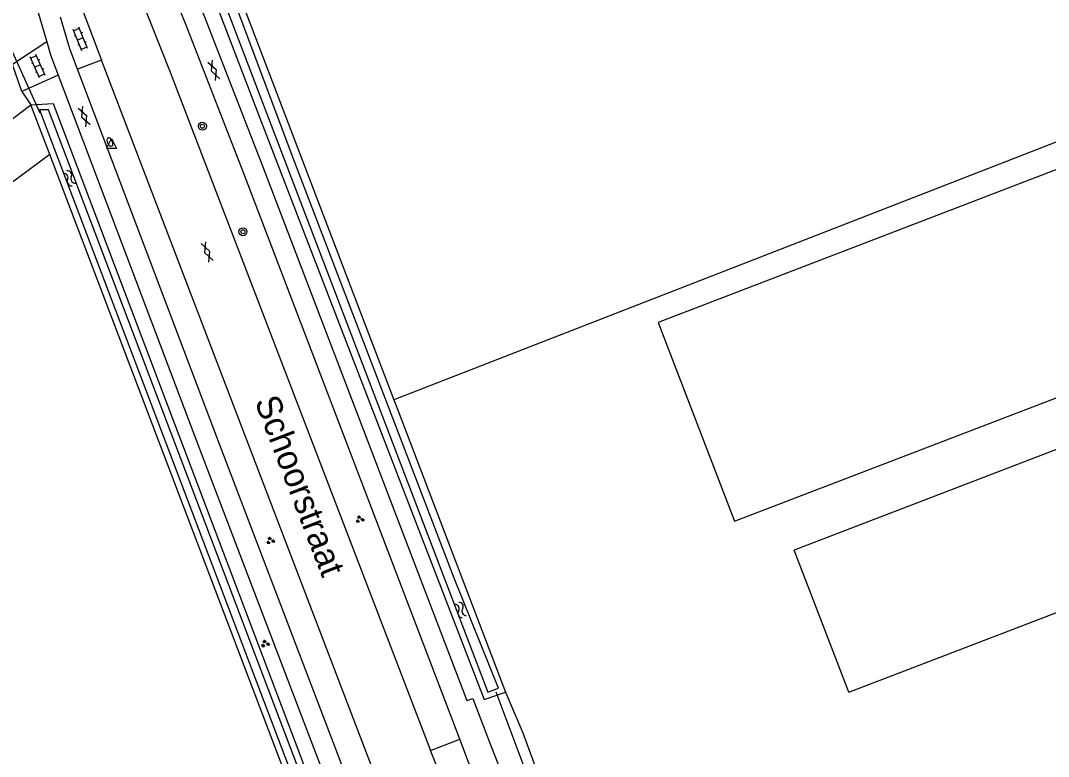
# Model space of a CAD drawing. Extents: x 134297 to 137000, y 403500 to 406000.
# Drawn here: x 136243.4 to 136346, y 404395.2 to 404468.7 of the extents above; entities that cross this region are included whole.
import ezdxf

# ---------------------------------------------------------------- set-up
doc = ezdxf.new("R2010")
doc.units = 0
for name, color, linetype in [('gg-anno-openbare ruimte label', 7, 'Continuous'), ('gg-bbg-bijgebouw', 7, 'Continuous'), ('gg-bbg-gedigitaliseerde bijgebouw', 7, 'Continuous'), ('gg-knt-bronhoudergrens', 7, 'Continuous'), ('gg-knt-verharding', 7, 'Continuous'), ('gg-kntw-bovenkant insteek waterloop', 7, 'Continuous'), ('gg-kntw-waterlijn', 7, 'Continuous'), ('gg-kwrk-duiker nz buis', 7, 'Continuous'), ('gt-grn-groengrens', 7, 'Continuous'), ('gt-grn-vlakafsluiter', 7, 'Continuous'), ('gt-symb-boom', 7, 'Continuous'), ('gt-symb-brandkraan', 7, 'Continuous'), ('gt-symb-gesloten verharding', 7, 'Continuous'), ('gt-symb-groenvak', 7, 'Continuous'), ('gt-symb-klinker verharding', 7, 'Continuous'), ('gt-symb-waterafsluiter', 7, 'Continuous'), ('gt-symb-watersymbool', 7, 'Continuous')]:
    doc.layers.add(name, color=color, linetype=linetype)

# ---------------------------------------------------------------- blocks, each defined once
blk = doc.blocks.new('gt0-WA')
at = {"layer": 'gt-symb-watersymbool'}
for centre, start, end in [((-0.32, 0.02), 28.0725, 151.9275), ((0.43, 0.42), 208.0725, 331.9275), ((-0.32, -0.43), 28.0725, 151.9275), ((0.43, -0.03), 208.0725, 331.9275)]:
    blk.add_arc(centre, 0.425, start, end, dxfattribs=at)
blk = doc.blocks.new('gt0-GRVAK')
at = {"layer": 'gt-symb-groenvak'}
for p, q in [((-0.11, 0.19), (-0.23, 0.24)), ((-0.18, 0.15), (0.09, 0.15)), ((-0.09, 0.21), (-0.16, 0.32)), ((-0.05, 0.21), (-0.05, 0.39)), ((0, 0.21), (0.06, 0.32)), ((0.01, 0.19), (0.13, 0.24)), ((0.26, -0.05), (0.2, 0.06)), ((0.3, -0.05), (0.3, 0.13)), ((0.35, -0.05), (0.41, 0.06)), ((-0.24, -0.23), (-0.36, -0.18)), ((-0.32, -0.26), (-0.05, -0.26)), ((-0.23, -0.21), (-0.29, -0.09)), ((-0.18, -0.2), (-0.18, -0.02)), ((-0.14, -0.21), (-0.07, -0.09)), ((-0.12, -0.23), (0, -0.18)), ((0.24, -0.07), (0.12, -0.02)), ((0.17, -0.11), (0.44, -0.11)), ((0.37, -0.07), (0.49, -0.02))]:
    blk.add_line(p, q, dxfattribs=at)
blk = doc.blocks.new('gt0-BOOM')
at = {"layer": 'gt-symb-boom'}
for radius in [0.4, 0.2]:
    blk.add_circle((0, 0), radius, dxfattribs=at)
blk = doc.blocks.new('gt0-GESVH1')
at = {"layer": 'gt-symb-gesloten verharding'}
for p, q in [((-0.99, -0.26), (0.01, 0.24)), ((0.01, -0.26), (-0.99, 0.24)), ((0.01, 0.24), (1.01, -0.26)), ((1.01, 0.24), (0.01, -0.26))]:
    blk.add_line(p, q, dxfattribs=at)
blk = doc.blocks.new('gt0-KL1')
at = {"layer": 'gt-symb-klinker verharding'}
for p, q in [((-1.15, 0.3), (1.15, 0.3)), ((-1, -0.3), (-1, 0.3)), ((-0.5, 0.3), (-0.5, 0.45)), ((0, -0.3), (0, 0.3)), ((0.5, 0.3), (0.5, 0.45)), ((1, -0.3), (1, 0.3)), ((-1.15, -0.3), (1.15, -0.3)), ((-0.5, -0.45), (-0.5, -0.3)), ((0.5, -0.45), (0.5, -0.3))]:
    blk.add_line(p, q, dxfattribs=at)
blk = doc.blocks.new('gt0-BR')
at = {"layer": 'gt-symb-brandkraan'}
for centre, radius, start, end in [((-0.24, 0), 0.206, 107.5669, 252.4331), ((0.6, -2.66), 3, 106.892, 107.5669), ((0, -0.69), 0.938, 73.108, 106.892), ((-0.6, -2.66), 3, 72.4331, 73.108), ((0.24, 0), 0.206, 287.567, 72.4331), ((0.6, 2.66), 3, 252.4331, 253.108), ((0, 0.69), 0.938, 253.108, 286.8921), ((-0.6, 2.66), 3, 286.8921, 287.567)]:
    blk.add_arc(centre, radius, start, end, dxfattribs=at)
blk = doc.blocks.new('gt0-WAFSL')
at = {"layer": 'gt-symb-waterafsluiter'}
for p, q in [((-0.5, -0.33), (0, 0.67)), ((0, 0.67), (0.5, -0.33)), ((0.5, -0.33), (-0.5, -0.33))]:
    blk.add_line(p, q, dxfattribs=at)

msp = doc.modelspace()

# ---------------------------------------------------------------- linework, layer by layer
at = {"layer": 'gg-bbg-bijgebouw'}
msp.add_line((136326.11, 404401.59), (136320.65, 404415.78), dxfattribs=at)
for points in [[(136361.56, 404436.66), (136353.94, 404456.51), (136307.08, 404438.52)], [(136307.08, 404438.52), (136314.7, 404418.67), (136361.56, 404436.66)]]:
    msp.add_lwpolyline(points, dxfattribs=at)
at = {"layer": 'gg-bbg-gedigitaliseerde bijgebouw'}
msp.add_lwpolyline([(136326.11, 404401.59), (136368.45, 404417.84), (136363.02, 404432.04), (136320.65, 404415.78)], dxfattribs=at)
at = {"layer": 'gg-knt-bronhoudergrens'}
for points in [[(136365.92, 404433.45), (136355.86, 404460.06), (136280.69, 404430.8)], [(136246.33, 404455.28), (136215.76, 404432.64), (136169.13, 404397.65), (136148.62, 404382.43)]]:
    msp.add_lwpolyline(points, dxfattribs=at)
at = {"layer": 'gg-knt-verharding'}
for p, q in [((136249.56, 404469.81), (136251.49, 404464.7)), ((136246.03, 404466.53), (136242.62, 404464.28)), ((136243.55, 404461.56), (136242.62, 404464.28)), ((136251.49, 404464.7), (136249.1, 404463.79)), ((136286.76, 404372.55), (136251.49, 404464.7)), ((136247.17, 404463.21), (136243.55, 404461.56)), ((136284.35, 404395.78), (136287.27, 404396.9)), ((136289.51, 404391.02), (136287.27, 404396.9)), ((136286.66, 404390), (136284.35, 404395.78)), ((136290.34, 404396.35), (136291.48, 404393.36))]:
    msp.add_line(p, q, dxfattribs=at)
for points in [[(136236.92, 404491.15), (136238.33, 404488.31), (136240.16, 404484.25), (136241.24, 404481.65), (136242.9, 404477.26), (136246.03, 404466.53)], [(136257.26, 404478.33), (136258.34, 404476.47), (136260.25, 404472.8), (136261.79, 404469.04), (136267.61, 404454.05), (136287.96, 404400.75), (136288.58, 404400.98), (136290.34, 404396.35)], [(136287.27, 404396.9), (136265.7, 404453.37), (136259.9, 404468.36), (136258.39, 404472.01), (136256.53, 404475.56), (136256, 404476.48)], [(136253.61, 404475.53), (136258.35, 404463.5), (136284.35, 404395.78)], [(136249.1, 404463.79), (136248.33, 404465.83), (136247.41, 404469.01)], [(136246.03, 404466.53), (136246.4, 404465.25), (136247.17, 404463.21)], [(136247.17, 404463.21), (136261.3, 404425.9), (136282.38, 404370.6)], [(136284.14, 404371.63), (136263.18, 404426.61), (136249.1, 404463.79)]]:
    msp.add_lwpolyline(points, dxfattribs=at)
at = {"layer": 'gg-kntw-bovenkant insteek waterloop'}
for p, q in [((136262.9, 404477.39), (136280.69, 404430.8)), ((136246.33, 404455.28), (136244.44, 404460.24)), ((136278.28, 404371.27), (136246.33, 404455.28)), ((136280.69, 404430.8), (136281.06, 404429.85)), ((136281.06, 404429.85), (136291.84, 404401.61)), ((136289.71, 404400.86), (136291.84, 404401.61))]:
    msp.add_line(p, q, dxfattribs=at)
for points in [[(136262.9, 404477.39), (136260.5, 404476.76), (136267.6, 404458.13), (136289.71, 404400.86)], [(136244.44, 404460.24), (136246.67, 404460.36), (136280.16, 404372), (136278.28, 404371.27)]]:
    msp.add_lwpolyline(points, dxfattribs=at)
at = {"layer": 'gg-kntw-waterlijn'}
for points in [[(136261.75, 404475.74), (136290.05, 404401.58), (136291.12, 404401.99), (136286.7, 404412.98), (136270.63, 404454.92), (136262.71, 404476.09), (136261.75, 404475.74)], [(136245.31, 404459.76), (136278.5, 404372.26), (136279.27, 404372.55), (136246.2, 404459.75), (136245.31, 404459.76)]]:
    msp.add_lwpolyline(points, dxfattribs=at)
at = {"layer": 'gg-kwrk-duiker nz buis'}
for p, q in [((136241.31, 404468.31), (136245.33, 404459.43)), ((136290.86, 404401.62), (136298.17, 404382.24))]:
    msp.add_line(p, q, dxfattribs=at)
at = {"layer": 'gt-grn-groengrens'}
for p, q in [((136243.55, 404461.56), (136244.44, 404460.24)), ((136291.84, 404401.61), (136293.55, 404397.55))]:
    msp.add_line(p, q, dxfattribs=at)
msp.add_lwpolyline([(136293.55, 404397.55), (136294.67, 404394.53), (136298.85, 404382.06)], dxfattribs=at)
at = {"layer": 'gt-grn-vlakafsluiter'}
msp.add_line((136128.9, 404372.27), (136244.44, 404460.24), dxfattribs=at)

# ---------------------------------------------------------------- block references
at = {"layer": 'gt-symb-boom'}
for p in [(136261.57, 404458.11), (136265.62, 404447.57)]:
    msp.add_blockref('gt0-BOOM', p, dxfattribs=at)
at = {"layer": 'gt-symb-brandkraan', "rotation": 114.9511516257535}
msp.add_blockref('gt0-BR', (136252.34, 404456.54), dxfattribs=at)
at = {"layer": 'gt-symb-gesloten verharding'}
for p, rotation in [((136262.71, 404463.67), 112.02484593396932), ((136249.77, 404459.07), 112.02484593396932), ((136262.05, 404445.53), 110.97171056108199)]:
    msp.add_blockref('gt0-GESVH1', p, dxfattribs=dict(at, rotation=rotation))
at = {"layer": 'gt-symb-groenvak'}
for p in [(136277.27, 404418.85), (136268.35, 404416.72), (136267.83, 404406.43)]:
    msp.add_blockref('gt0-GRVAK', p, dxfattribs=at)
at = {"layer": 'gt-symb-klinker verharding'}
for p, rotation in [((136249.38, 404466.82), 111.89715058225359), ((136245.13, 404464.11), 114.00319024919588)]:
    msp.add_blockref('gt0-KL1', p, dxfattribs=dict(at, rotation=rotation))
at = {"layer": 'gt-symb-waterafsluiter'}
msp.add_blockref('gt0-WAFSL', (136252.49, 404456.22), dxfattribs=at)
at = {"layer": 'gt-symb-watersymbool'}
for p, rotation in [((136248.33, 404452.86), 126.01052540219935), ((136287.37, 404409.75), 118.99897714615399)]:
    msp.add_blockref('gt0-WA', p, dxfattribs=dict(at, rotation=rotation))

# ---------------------------------------------------------------- texts
at = {"layer": 'gg-anno-openbare ruimte label'}
msp.add_text('Schoorstraat', height=2.5, rotation=291, dxfattribs=at).set_placement((136266.76, 404430.64))

doc.saveas('drawing.dxf')
